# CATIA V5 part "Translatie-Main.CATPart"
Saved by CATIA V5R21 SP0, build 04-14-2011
Part number: Translatie-main
Bounding box of the stored display mesh (mm): x -60 to 60, y -15 to 15, z 40 to 749.5
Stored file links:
  C:\Users\MIRCEA\Desktop\PRRO\CATIAV5\Translatie-Main.CATPart
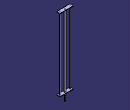
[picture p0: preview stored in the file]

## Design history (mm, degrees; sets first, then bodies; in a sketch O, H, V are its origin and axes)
Body1 (main body)
  Plane1: type Offset, RefPlane xy-plane, Offset 40
  Sketch1 on Plane1, origin (0, 0, 40), H (1, 0, 0), V (0, 1, 0)
    circle A1 centre (0, 0) radius 2.5
    radius A1 = 2.5
  Pad1: profile Sketch1, direction (0, 0, 1), length 20
  Plane2: type Offset, RefPlane Plane1, Offset 20
  Sketch2 on Plane2, origin (0, 0, 60), H (1, 0, 0), V (0, 1, 0)
    circle A1 centre (0, 0) radius 4
    radius A1 = 4
  Pad2: profile Sketch2, direction (0, 0, 1), length 14
  Plane3: type Offset, RefPlane Plane2, Offset 13
  Sketch3 on Plane3, origin (0, 0, 73), H (1, 0, 0), V (0, 1, 0)
    circle A1 centre (0, 0) radius 4.5
    radius A1 = 4.5
  Pad3: profile Sketch3, direction (0, 0, 1), length 15
  Plane4: type Offset, RefPlane xy-plane, Offset 1.75
  Plane5: type Offset, RefPlane Plane3, Offset 15
  Sketch4 on Plane5, origin (0, 0, 88), H (1, 0, 0), V (0, 1, 0)
    circle A1 centre (0, 0) radius 6
    radius A1 = 6
  Pad4: profile Sketch4, direction (0, 0, 1), length 20
  Plane6: type Offset, RefPlane Plane5, Offset 20
  Sketch5 on Plane6, origin (0, 0, 108), H (1, 0, 0), V (0, 1, 0)
    circle A1 centre (0, 0) radius 8
    radius A1 = 8
  Pad5: profile Sketch5, direction (0, 0, 1), length 5
  Plane7: type Offset, RefPlane Plane6, Offset 5
  Sketch6 on Plane7, origin (0, 0, 113), H (1, 0, 0), V (0, 1, 0)
    circle A1 centre (0, 0) radius 6
    radius A1 = 6
  Pad6: profile Sketch6, direction (0, 0, 1), length 634
  Plane8: type Offset, RefPlane zx-plane, Offset 2.5
  Sketch7 on Plane8, origin (0, 2.5, 0), H (-1, 0, 0), V (0, 0, 1)
    construction line L1 (0, 42) -> (0, 47)
    line L2 (-1, 42) -> (-1, 47)
    line L3 (1, 47) -> (1, 42)
    arc A1 centre (0, 47) radius 1 from (-1, 47) to (1, 47) cw
    arc A2 centre (0, 42) radius 1 from (1, 42) to (-1, 42) cw
    length L1 = 5
    distance L1 L2 = 1
    vertical: L1 V
    tangency: A1 L2, A2 L2, A1 L3, A2 L3
  Pocket1: profile Sketch7, direction (0, -1, 0), length 1.5
  Plane9: type Offset, RefPlane Plane6, Offset 2.5
  Sketch8 on Plane9, origin (0, 0, 110.5), H (1, 0, 0), V (0, 1, 0)
    line L1 (60, 15) -> (60, -15)
    line L2 (60, -15) -> (-60, -15)
    line L3 (-60, -15) -> (-60, 15)
    line L4 (-60, 15) -> (60, 15)
    point P1 (60, 15)
    distance P1 H = 15
    distance P1 V = 60
    vertical: L1 V, L3 V
    horizontal: L2 H, L4 H
    equidistance: L1 L3 O, L2 L4 O
  Pad7: profile Sketch8, direction (0, 0, 1), length 2.5
  Plane10: type Offset, RefPlane Plane6, Offset 639
  Sketch9 on Plane10, origin (0, 0, 747), H (1, 0, 0), V (0, 1, 0)
    line L1 (60, 15) -> (60, -15)
    line L2 (60, -15) -> (-60, -15)
    line L3 (-60, -15) -> (-60, 15)
    line L4 (-60, 15) -> (60, 15)
    point P1 (60, 15)
    distance P1 H = 15
    distance P1 V = 60
    vertical: L1 V, L3 V
    horizontal: L2 H, L4 H
    equidistance: L1 L3 O, L2 L4 O
  Pad8: profile Sketch9, direction (0, 0, 1), length 2.5
  Sketch10 on Plane7, origin (0, 0, 113), H (1, 0, 0), V (0, 1, 0)
    circle A1 centre (45, 0) radius 4.2
    circle A2 centre (-45, 0) radius 4.2
    radius A1 = 4.2
    radius A2 = 4.2
  Pad9: profile Sketch10, direction (0, 0, 1), length 634
  Chamfer1: length 3, angle 45, on edge [face of Pad7 from Sketch8.L3 | face of Pad7 from Sketch8.L4]; edge [face of Pad7 from Sketch8.L2 | face of Pad7 from Sketch8.L3]; edge [face of Pad7 from Sketch8.L1 | face of Pad7 from Sketch8.L2]; edge [face of Pad7 from Sketch8.L4 | face of Pad7 from Sketch8.L1]; edge [face of Pad8 from Sketch9.L3 | face of Pad8 from Sketch9.L4]; edge [face of Pad8 from Sketch9.L2 | face of Pad8 from Sketch9.L3]; edge [face of Pad8 from Sketch9.L4 | face of Pad8 from Sketch9.L1]; edge [face of Pad8 from Sketch9.L1 | face of Pad8 from Sketch9.L2]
